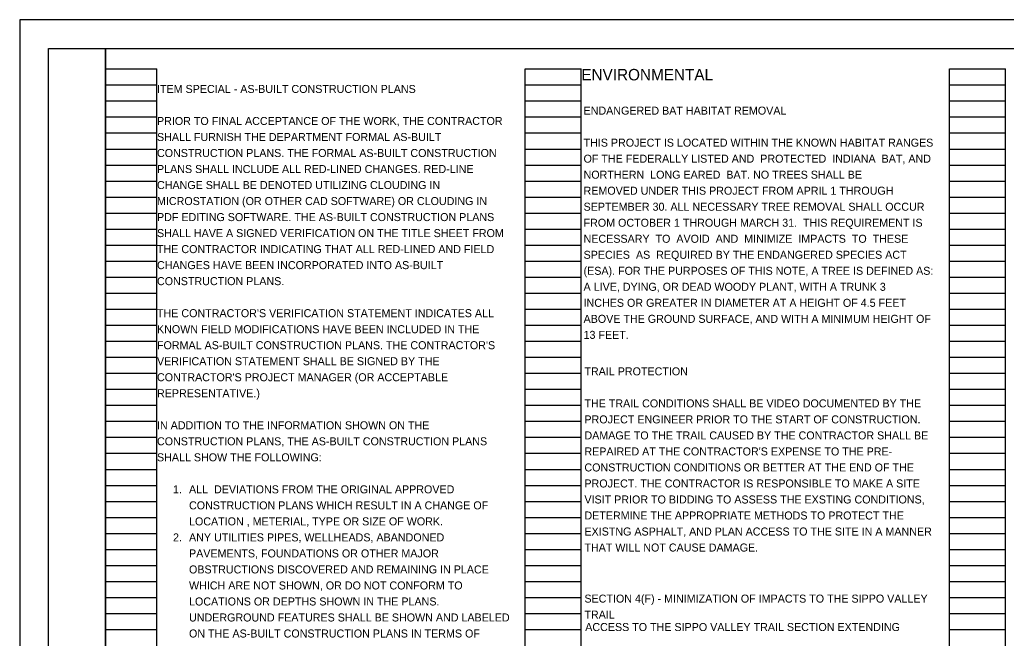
# Model space of a CAD drawing. Extents: x 4.7 to 38.7, y 13.7 to 35.7.
# Drawn here: x 4.7 to 21.96, y 24.9 to 35.71 of the extents above; entities that cross this region are included whole.
import ezdxf

# ---------------------------------------------------------------- set-up
doc = ezdxf.new("R2010")
doc.units = 0
for name, color, linetype in [('SH_Border', 7, 'Continuous'), ('SH_Cut_Line', 7, 'Continuous'), ('SH_Data', 7, 'Continuous'), ('SH_Text', 7, 'Continuous')]:
    doc.layers.add(name, color=color, linetype=linetype)

msp = doc.modelspace()

# ---------------------------------------------------------------- linework, layer by layer
at = {"layer": 'SH_Border'}
for points in [[(5.205, 35.212), (6.205, 35.212), (6.205, 14.212), (5.205, 14.212)], [(6.205, 35.212), (38.205, 35.212), (38.205, 14.212), (6.205, 14.212)]]:
    msp.add_lwpolyline(points, close=True, dxfattribs=at)
at = {"layer": 'SH_Cut_Line'}
msp.add_lwpolyline([(4.705, 13.712), (38.705, 13.712), (38.705, 35.712), (4.705, 35.712)], close=True, dxfattribs=at)
at = {"layer": 'SH_Data'}
for p, q in [((6.205, 14.692), (6.205, 34.852)), ((6.205, 34.852), (7.105, 34.852)), ((7.105, 14.692), (7.105, 34.852)), ((13.545, 14.692), (13.545, 34.852)), ((13.545, 34.852), (14.525, 34.852)), ((14.525, 14.692), (14.525, 34.852)), ((20.965, 14.692), (20.965, 34.852)), ((20.965, 34.852), (21.945, 34.852)), ((21.945, 14.692), (21.945, 34.852)), ((6.205, 34.572), (7.105, 34.572)), ((13.545, 34.572), (14.525, 34.572)), ((20.965, 34.572), (21.945, 34.572)), ((6.205, 34.292), (7.105, 34.292)), ((13.545, 34.292), (14.525, 34.292)), ((20.965, 34.292), (21.945, 34.292)), ((6.205, 34.012), (7.105, 34.012)), ((13.545, 34.012), (14.525, 34.012)), ((20.965, 34.012), (21.945, 34.012)), ((6.205, 33.732), (7.105, 33.732)), ((13.545, 33.732), (14.525, 33.732)), ((20.965, 33.732), (21.945, 33.732)), ((6.205, 33.452), (7.105, 33.452)), ((13.545, 33.452), (14.525, 33.452)), ((20.965, 33.452), (21.945, 33.452)), ((6.205, 33.172), (7.105, 33.172)), ((13.545, 33.172), (14.525, 33.172)), ((20.965, 33.172), (21.945, 33.172)), ((6.205, 32.892), (7.105, 32.892)), ((13.545, 32.892), (14.525, 32.892)), ((20.965, 32.892), (21.945, 32.892)), ((6.205, 32.612), (7.105, 32.612)), ((13.545, 32.612), (14.525, 32.612)), ((20.965, 32.612), (21.945, 32.612)), ((6.205, 32.332), (7.105, 32.332)), ((13.545, 32.332), (14.525, 32.332)), ((20.965, 32.332), (21.945, 32.332)), ((6.205, 32.052), (7.105, 32.052)), ((13.545, 32.052), (14.525, 32.052)), ((20.965, 32.052), (21.945, 32.052)), ((6.205, 31.772), (7.105, 31.772)), ((13.545, 31.772), (14.525, 31.772)), ((20.965, 31.772), (21.945, 31.772)), ((6.205, 31.492), (7.105, 31.492)), ((13.545, 31.492), (14.525, 31.492)), ((20.965, 31.492), (21.945, 31.492)), ((6.205, 31.212), (7.105, 31.212)), ((13.545, 31.212), (14.525, 31.212)), ((20.965, 31.212), (21.945, 31.212)), ((6.205, 30.932), (7.105, 30.932)), ((13.545, 30.932), (14.525, 30.932)), ((20.965, 30.932), (21.945, 30.932)), ((6.205, 30.652), (7.105, 30.652)), ((13.545, 30.652), (14.525, 30.652)), ((20.965, 30.652), (21.945, 30.652)), ((6.205, 30.372), (7.105, 30.372)), ((13.545, 30.372), (14.525, 30.372)), ((20.965, 30.372), (21.945, 30.372)), ((6.205, 30.092), (7.105, 30.092)), ((13.545, 30.092), (14.525, 30.092)), ((20.965, 30.092), (21.945, 30.092)), ((6.205, 29.812), (7.105, 29.812)), ((13.545, 29.812), (14.525, 29.812)), ((20.965, 29.812), (21.945, 29.812)), ((6.205, 29.532), (7.105, 29.532)), ((13.545, 29.532), (14.525, 29.532)), ((20.965, 29.532), (21.945, 29.532)), ((6.205, 29.252), (7.105, 29.252)), ((13.545, 29.252), (14.525, 29.252)), ((20.965, 29.252), (21.945, 29.252)), ((6.205, 28.972), (7.105, 28.972)), ((13.545, 28.972), (14.525, 28.972)), ((20.965, 28.972), (21.945, 28.972)), ((6.205, 28.692), (7.105, 28.692)), ((13.545, 28.692), (14.525, 28.692)), ((20.965, 28.692), (21.945, 28.692)), ((6.205, 28.412), (7.105, 28.412)), ((13.545, 28.412), (14.525, 28.412)), ((20.965, 28.412), (21.945, 28.412)), ((6.205, 28.132), (7.105, 28.132)), ((13.545, 28.132), (14.525, 28.132)), ((20.965, 28.132), (21.945, 28.132)), ((6.205, 27.852), (7.105, 27.852)), ((13.545, 27.852), (14.525, 27.852)), ((20.965, 27.852), (21.945, 27.852)), ((6.205, 27.572), (7.105, 27.572)), ((13.545, 27.572), (14.525, 27.572)), ((20.965, 27.572), (21.945, 27.572)), ((6.205, 27.292), (7.105, 27.292)), ((13.545, 27.292), (14.525, 27.292)), ((20.965, 27.292), (21.945, 27.292)), ((6.205, 27.012), (7.105, 27.012)), ((13.545, 27.012), (14.525, 27.012)), ((20.965, 27.012), (21.945, 27.012)), ((6.205, 26.732), (7.105, 26.732)), ((13.545, 26.732), (14.525, 26.732)), ((20.965, 26.732), (21.945, 26.732)), ((6.205, 26.452), (7.105, 26.452)), ((13.545, 26.452), (14.525, 26.452)), ((20.965, 26.452), (21.945, 26.452)), ((6.205, 26.172), (7.105, 26.172)), ((13.545, 26.172), (14.525, 26.172)), ((20.965, 26.172), (21.945, 26.172)), ((6.205, 25.892), (7.105, 25.892)), ((13.545, 25.892), (14.525, 25.892)), ((20.965, 25.892), (21.945, 25.892)), ((6.205, 25.612), (7.105, 25.612)), ((13.545, 25.612), (14.525, 25.612)), ((20.965, 25.612), (21.945, 25.612)), ((6.205, 25.332), (7.105, 25.332)), ((13.545, 25.332), (14.525, 25.332)), ((20.965, 25.332), (21.945, 25.332)), ((6.205, 25.052), (7.105, 25.052)), ((13.545, 25.052), (14.525, 25.052)), ((20.965, 25.052), (21.945, 25.052))]:
    msp.add_line(p, q, dxfattribs=at)

# ---------------------------------------------------------------- texts
at = {"layer": 'SH_Text'}
for s, height, p in [('ENVIRONMENTAL', 0.2, (14.525, 34.652)), ('ITEM SPECIAL - AS-BUILT CONSTRUCTION PLANS', 0.14, (7.105, 34.432)), ('ENDANGERED BAT HABITAT REMOVAL', 0.14, (14.564, 34.053)), ('PRIOR TO FINAL ACCEPTANCE OF THE WORK, THE CONTRACTOR ', 0.14, (7.105, 33.872)), ('SHALL FURNISH THE DEPARTMENT FORMAL AS-BUILT ', 0.14, (7.105, 33.592)), ('THIS PROJECT IS LOCATED WITHIN THE KNOWN HABITAT RANGES ', 0.14, (14.564, 33.493)), ('CONSTRUCTION PLANS. THE FORMAL AS-BUILT CONSTRUCTION ', 0.14, (7.105, 33.312)), ('OF THE FEDERALLY LISTED AND  PROTECTED  INDIANA  BAT, AND  ', 0.14, (14.564, 33.213)), ('PLANS SHALL INCLUDE ALL RED-LINED CHANGES. RED-LINE ', 0.14, (7.105, 33.032)), ('NORTHERN  LONG EARED  BAT. NO TREES SHALL BE ', 0.14, (14.564, 32.933)), ('CHANGE SHALL BE DENOTED UTILIZING CLOUDING IN ', 0.14, (7.105, 32.752)), ('REMOVED UNDER THIS PROJECT FROM APRIL 1 THROUGH ', 0.14, (14.564, 32.653)), ('MICROSTATION (OR OTHER CAD SOFTWARE) OR CLOUDING IN ', 0.14, (7.105, 32.472)), ('SEPTEMBER 30. ALL NECESSARY TREE REMOVAL SHALL OCCUR ', 0.14, (14.564, 32.373)), ('PDF EDITING SOFTWARE. THE AS-BUILT CONSTRUCTION PLANS ', 0.14, (7.105, 32.192)), ('FROM OCTOBER 1 THROUGH MARCH 31.  THIS REQUIREMENT IS ', 0.14, (14.564, 32.093)), ('SHALL HAVE A SIGNED VERIFICATION ON THE TITLE SHEET FROM ', 0.14, (7.105, 31.912)), ('NECESSARY  TO  AVOID  AND  MINIMIZE  IMPACTS  TO  THESE  ', 0.14, (14.564, 31.813)), ('THE CONTRACTOR INDICATING THAT ALL RED-LINED AND FIELD ', 0.14, (7.105, 31.632)), ('SPECIES  AS  REQUIRED BY THE ENDANGERED SPECIES ACT ', 0.14, (14.564, 31.533)), ('CHANGES HAVE BEEN INCORPORATED INTO AS-BUILT ', 0.14, (7.105, 31.352)), ('(ESA). FOR THE PURPOSES OF THIS NOTE, A TREE IS DEFINED AS: ', 0.14, (14.564, 31.253)), ('CONSTRUCTION PLANS. ', 0.14, (7.105, 31.072)), ('A LIVE, DYING, OR DEAD WOODY PLANT, WITH A TRUNK 3', 0.14, (14.564, 30.973)), ('INCHES OR GREATER IN DIAMETER AT A HEIGHT OF 4.5 FEET ', 0.14, (14.564, 30.693)), ("THE CONTRACTOR'S VERIFICATION STATEMENT INDICATES ALL ", 0.14, (7.105, 30.512)), ('ABOVE THE GROUND SURFACE, AND WITH A MINIMUM HEIGHT OF ', 0.14, (14.564, 30.413)), ('KNOWN FIELD MODIFICATIONS HAVE BEEN INCLUDED IN THE ', 0.14, (7.105, 30.232)), ('13 FEET.', 0.14, (14.564, 30.133)), ("FORMAL AS-BUILT CONSTRUCTION PLANS. THE CONTRACTOR'S ", 0.14, (7.105, 29.952)), ('VERIFICATION STATEMENT SHALL BE SIGNED BY THE ', 0.14, (7.105, 29.672)), ("CONTRACTOR'S PROJECT MANAGER (OR ACCEPTABLE ", 0.14, (7.105, 29.392)), ('TRAIL PROTECTION', 0.14, (14.579, 29.495)), ('REPRESENTATIVE.)', 0.14, (7.105, 29.112)), ('THE TRAIL CONDITIONS SHALL BE VIDEO DOCUMENTED BY THE ', 0.14, (14.579, 28.935)), ('IN ADDITION TO THE INFORMATION SHOWN ON THE ', 0.14, (7.105, 28.552)), ('PROJECT ENGINEER PRIOR TO THE START OF CONSTRUCTION. ', 0.14, (14.579, 28.655)), ('DAMAGE TO THE TRAIL CAUSED BY THE CONTRACTOR SHALL BE ', 0.14, (14.579, 28.375)), ('CONSTRUCTION PLANS, THE AS-BUILT CONSTRUCTION PLANS ', 0.14, (7.105, 28.272)), ('SHALL SHOW THE FOLLOWING:', 0.14, (7.105, 27.992)), ("REPAIRED AT THE CONTRACTOR'S EXPENSE TO THE PRE-", 0.14, (14.579, 28.095)), ('CONSTRUCTION CONDITIONS OR BETTER AT THE END OF THE ', 0.14, (14.579, 27.815)), ('PROJECT. THE CONTRACTOR IS RESPONSIBLE TO MAKE A SITE ', 0.14, (14.579, 27.535)), ('1.', 0.14, (7.385, 27.432)), ('ALL  DEVIATIONS FROM THE ORIGINAL APPROVED ', 0.14, (7.665, 27.432)), ('CONSTRUCTION PLANS WHICH RESULT IN A CHANGE OF ', 0.14, (7.665, 27.152)), ('VISIT PRIOR TO BIDDING TO ASSESS THE EXSTING CONDITIONS, ', 0.14, (14.579, 27.255)), ('DETERMINE THE APPROPRIATE METHODS TO PROTECT THE ', 0.14, (14.579, 26.975)), ('LOCATION , METERIAL, TYPE OR SIZE OF WORK.', 0.14, (7.665, 26.872)), ('EXISTNG ASPHALT, AND PLAN ACCESS TO THE SITE IN A MANNER ', 0.14, (14.579, 26.695)), ('2.', 0.14, (7.385, 26.592)), ('ANY UTILITIES PIPES, WELLHEADS, ABANDONED ', 0.14, (7.665, 26.592)), ('PAVEMENTS, FOUNDATIONS OR OTHER MAJOR ', 0.14, (7.665, 26.312)), ('THAT WILL NOT CAUSE DAMAGE. ', 0.14, (14.579, 26.415)), ('OBSTRUCTIONS DISCOVERED AND REMAINING IN PLACE ', 0.14, (7.665, 26.032)), ('WHICH ARE NOT SHOWN, OR DO NOT CONFORM TO ', 0.14, (7.665, 25.752)), ('LOCATIONS OR DEPTHS SHOWN IN THE PLANS. ', 0.14, (7.665, 25.472)), ('SECTION 4(F) - MINIMIZATION OF IMPACTS TO THE SIPPO VALLEY ', 0.14, (14.579, 25.522)), ('TRAIL', 0.14, (14.579, 25.242)), ('UNDERGROUND FEATURES SHALL BE SHOWN AND LABELED ', 0.14, (7.665, 25.192)), ('ON THE AS-BUILT CONSTRUCTION PLANS IN TERMS OF ', 0.14, (7.665, 24.912)), ('ACCESS TO THE SIPPO VALLEY TRAIL SECTION EXTENDING ', 0.14, (14.593, 25.025))]:
    msp.add_text(s, height=height, dxfattribs=at).set_placement(p)

doc.saveas('drawing.dxf')
